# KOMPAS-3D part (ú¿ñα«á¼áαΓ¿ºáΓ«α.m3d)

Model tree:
1. Эскиз:1
2. Операция выдавливания:1
     Расстояние 1 = 0.5
3. Эскиз:2
4. Операция выдавливания:2
     Расстояние 1 = 0.5
5. Эскиз:3
6. Операция выдавливания:3
     Расстояние 1 = 1
7. Эскиз:4
8. Операция выдавливания:4
     Расстояние 1 = 0.5
9. Эскиз:5
10. Вырезать элемент выдавливания:1
     Расстояние 1 = 1
11. Эскиз:6
12. Операция выдавливания:5
     Расстояние 1 = 1
13. Эскиз:7
14. Операция выдавливания:6
     Расстояние 1 = 0.3
15. Массив по концентрической сетке:1  (with: Операция выдавливания:6)  (labels: Экземпляр ( 1, 1 ); Экземпляр ( 1, 2 ); Экземпляр ( 1, 3 ); Экземпляр ( 1, 4 ))
     N 2 = 10; Шаг 2 = 360; Номер 2 = 1
16. Эскиз:8
17. Операция выдавливания:7
     Расстояние 1 = 0.5
18. Скругление:1
     Радиус = 1
19. Скругление:2
     Радиус = 0.1
20. Эскиз:9
21. Вырезать элемент выдавливания:2
     Расстояние 1 = 0.5
22. Массив по концентрической сетке:2  (with: Вырезать элемент выдавливания:2)  (labels: Экземпляр ( 1, 1 ); Экземпляр ( 1, 2 ); Экземпляр ( 1, 3 ); Экземпляр ( 1, 4 ))
     N 2 = 10; Шаг 2 = 360; Номер 2 = 1
23. Скругление:3
     Радиус = 0.1

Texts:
  Сплав АЛ8  ГОСТ 1583-93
